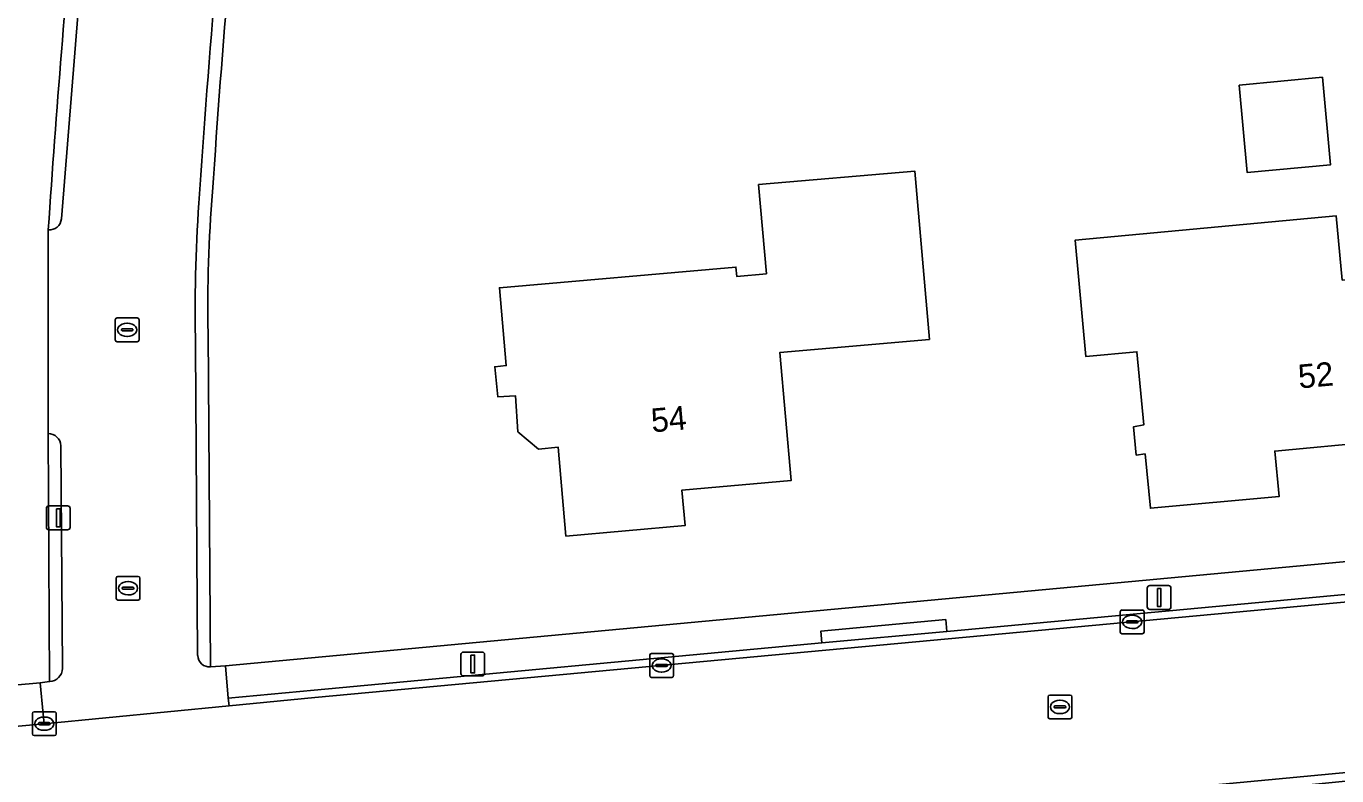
# Model space of a CAD drawing. Extents: x 162156 to 163172, y 378995 to 380779.
# Drawn here: x 162325.6 to 162380.6, y 380632.2 to 380663.7 of the extents above; entities that cross this region are included whole.
import ezdxf

# ---------------------------------------------------------------- set-up
doc = ezdxf.new("R2010")
doc.units = 0
for name, color, linetype in [('IMGEO_Erf', 7, 'Continuous'), ('IMGEO_Kolk', 7, 'Continuous'), ('IMGEO_Lichtmast', 7, 'Continuous'), ('IMGEO_Pand', 7, 'Continuous'), ('IMGEO_Pand_nummerreeks', 7, 'Continuous'), ('IMGEO_Rijbaan_lokaal_gesloten', 7, 'Continuous'), ('IMGEO_Rijbaan_lokaal_open', 7, 'Continuous'), ('IMGEO_Rioolput', 7, 'Continuous'), ('IMGEO_Voetpad_open', 7, 'Continuous')]:
    doc.layers.add(name, color=color, linetype=linetype)

msp = doc.modelspace()

# ---------------------------------------------------------------- linework, layer by layer
at = {"layer": 'IMGEO_Erf'}
for points in [[(162376.484, 380661.264), (162379.983, 380661.591), (162380.326, 380657.914), (162376.827, 380657.587)], [(162363.48, 380650.578), (162357.203, 380650.031), (162357.671, 380644.651), (162353.088, 380644.251), (162353.218, 380642.756), (162348.214, 380642.32), (162347.889, 380646.056), (162347.058, 380645.965), (162346.202, 380646.698), (162346.103, 380648.206), (162345.363, 380648.161), (162345.227, 380649.428), (162345.712, 380649.479), (162345.426, 380652.752), (162355.358, 380653.617), (162355.391, 380653.228), (162356.636, 380653.336), (162356.309, 380657.081), (162362.864, 380657.652)], [(162388.495, 380653.791), (162388.751, 380651.01), (162389.209, 380646.031), (162382.252, 380645.37), (162382.145, 380646.271), (162377.984, 380645.891), (162378.165, 380643.978), (162372.76, 380643.485), (162372.536, 380645.772), (162372.166, 380645.718), (162372.052, 380646.911), (162372.486, 380646.993), (162372.198, 380650.062), (162370.052, 380649.857), (162369.599, 380654.743), (162380.566, 380655.767), (162380.818, 380653.074)]]:
    msp.add_lwpolyline(points, close=True, dxfattribs=at)
for points in [[(162313.193, 380634.993), (162326.139, 380636.156), (162326.53, 380636.206), (162326.471, 380646.623), (162326.48, 380655.187)], [(162333.191, 380650.844), (162333.284, 380636.819), (162333.922, 380636.869), (162421.612, 380645.024), (162422.469, 380645.107), (162421.979, 380654.811)]]:
    msp.add_lwpolyline(points, dxfattribs=at)
for centre, radius, start, end in [((162806.048, 380625.746), 473.688, 174.0115, 176.24301), ((162859.206, 380619.711), 533.906, 174.58014, 176.19009), ((162390.909, 380652), 57.729, 175.24639, 181.14729)]:
    msp.add_arc(centre, radius, start, end, dxfattribs=at)
at = {"layer": 'IMGEO_Kolk'}
for p, q in [((162329.29, 380650.556), (162329.29, 380651.408)), ((162329.365, 380651.482), (162330.217, 380651.482)), ((162330.291, 380651.408), (162330.291, 380650.556)), ((162329.549, 380650.976), (162329.549, 380650.988)), ((162329.987, 380650.939), (162329.589, 380650.939)), ((162329.592, 380651.025), (162329.99, 380651.025)), ((162329.778, 380651.262), (162329.803, 380651.262)), ((162330.033, 380650.988), (162330.033, 380650.976)), ((162330.217, 380650.482), (162329.365, 380650.482)), ((162329.801, 380650.702), (162329.776, 380650.702)), ((162329.327, 380639.699), (162329.327, 380640.551)), ((162329.402, 380640.625), (162330.254, 380640.625)), ((162329.815, 380640.405), (162329.84, 380640.405)), ((162330.328, 380640.551), (162330.328, 380639.699)), ((162329.586, 380640.119), (162329.586, 380640.131)), ((162330.024, 380640.082), (162329.626, 380640.082)), ((162329.629, 380640.168), (162330.027, 380640.168)), ((162329.838, 380639.845), (162329.813, 380639.845)), ((162330.07, 380640.131), (162330.07, 380640.119)), ((162330.254, 380639.625), (162329.402, 380639.625)), ((162371.493, 380638.285), (162371.493, 380639.137)), ((162371.568, 380639.211), (162372.42, 380639.211)), ((162371.752, 380638.705), (162371.752, 380638.717)), ((162371.795, 380638.754), (162372.193, 380638.754)), ((162371.981, 380638.991), (162372.006, 380638.991)), ((162372.236, 380638.717), (162372.236, 380638.705)), ((162372.494, 380639.137), (162372.494, 380638.285)), ((162372.42, 380638.211), (162371.568, 380638.211)), ((162372.19, 380638.668), (162371.792, 380638.668)), ((162372.004, 380638.431), (162371.979, 380638.431)), ((162351.736, 380636.456), (162351.736, 380637.308)), ((162351.811, 380637.382), (162352.663, 380637.382)), ((162352.224, 380637.162), (162352.249, 380637.162)), ((162352.737, 380637.308), (162352.737, 380636.456)), ((162351.995, 380636.876), (162351.995, 380636.888)), ((162352.433, 380636.839), (162352.035, 380636.839)), ((162352.038, 380636.925), (162352.436, 380636.925)), ((162352.247, 380636.602), (162352.222, 380636.602)), ((162352.479, 380636.888), (162352.479, 380636.876)), ((162352.663, 380636.382), (162351.811, 380636.382)), ((162325.81, 380634.01), (162325.81, 380634.862)), ((162325.885, 380634.936), (162326.737, 380634.936)), ((162326.811, 380634.862), (162326.811, 380634.01)), ((162326.069, 380634.43), (162326.069, 380634.442)), ((162326.507, 380634.393), (162326.109, 380634.393)), ((162326.112, 380634.479), (162326.51, 380634.479)), ((162326.298, 380634.716), (162326.323, 380634.716)), ((162326.553, 380634.442), (162326.553, 380634.43)), ((162326.737, 380633.936), (162325.885, 380633.936)), ((162326.321, 380634.156), (162326.296, 380634.156))]:
    msp.add_line(p, q, dxfattribs=at)
for points in [[(162329.29, 380650.556), (162329.29, 380651.408)], [(162329.365, 380651.482), (162330.217, 380651.482)], [(162330.291, 380651.408), (162330.291, 380650.556)], [(162330.217, 380650.482), (162329.365, 380650.482)], [(162329.327, 380639.699), (162329.327, 380640.551)], [(162329.402, 380640.625), (162330.254, 380640.625)], [(162330.328, 380640.551), (162330.328, 380639.699)], [(162330.254, 380639.625), (162329.402, 380639.625)], [(162371.493, 380638.285), (162371.493, 380639.137)], [(162371.568, 380639.211), (162372.42, 380639.211)], [(162372.494, 380639.137), (162372.494, 380638.285)], [(162372.42, 380638.211), (162371.568, 380638.211)], [(162351.736, 380636.456), (162351.736, 380637.308)], [(162351.811, 380637.382), (162352.663, 380637.382)], [(162352.737, 380637.308), (162352.737, 380636.456)], [(162352.663, 380636.382), (162351.811, 380636.382)], [(162325.81, 380634.01), (162325.81, 380634.862)], [(162325.885, 380634.936), (162326.737, 380634.936)], [(162326.811, 380634.862), (162326.811, 380634.01)], [(162326.737, 380633.936), (162325.885, 380633.936)]]:
    msp.add_lwpolyline(points, dxfattribs=at)
for centre, radius, start, end in [((162329.367, 380651.406), 0.0765, 91.552, 178.448), ((162329.367, 380651.406), 0.0765, 91.552, 178.448), ((162330.215, 380651.406), 0.0765, 1.552, 88.448), ((162330.215, 380651.406), 0.0765, 1.552, 88.448), ((162329.589, 380650.985), 0.0403, 85.8775, 175.7526), ((162329.586, 380650.975), 0.0366, 178.938, 274.7102), ((162329.99, 380650.982), 0.043, 264.8664, 352.4533), ((162329.994, 380650.987), 0.0386, 1.7309, 96.639), ((162329.367, 380650.558), 0.0765, 181.552, 268.448), ((162329.367, 380650.558), 0.0765, 181.552, 268.448), ((162330.215, 380650.558), 0.0765, 271.552, 358.448), ((162330.215, 380650.558), 0.0765, 271.552, 358.448), ((162329.404, 380640.549), 0.0765, 91.552, 178.448), ((162329.404, 380640.549), 0.0765, 91.552, 178.448), ((162330.252, 380640.549), 0.0765, 1.552, 88.448), ((162330.252, 380640.549), 0.0765, 1.552, 88.448), ((162329.626, 380640.128), 0.0403, 85.8775, 175.7526), ((162329.623, 380640.118), 0.0366, 178.938, 274.7102), ((162330.027, 380640.125), 0.043, 264.8664, 352.4533), ((162330.031, 380640.13), 0.0386, 1.7309, 96.639), ((162329.404, 380639.701), 0.0765, 181.552, 268.448), ((162329.404, 380639.701), 0.0765, 181.552, 268.448), ((162330.252, 380639.701), 0.0765, 271.552, 358.448), ((162330.252, 380639.701), 0.0765, 271.552, 358.448), ((162371.57, 380639.135), 0.0765, 91.552, 178.448), ((162371.57, 380639.135), 0.0765, 91.552, 178.448), ((162371.792, 380638.714), 0.0403, 85.8775, 175.7526), ((162372.197, 380638.716), 0.0386, 1.7309, 96.639), ((162372.418, 380639.135), 0.0765, 1.552, 88.448), ((162372.418, 380639.135), 0.0765, 1.552, 88.448), ((162371.57, 380638.287), 0.0765, 181.552, 268.448), ((162371.57, 380638.287), 0.0765, 181.552, 268.448), ((162371.789, 380638.704), 0.0366, 178.938, 274.7102), ((162372.193, 380638.711), 0.043, 264.8664, 352.4533), ((162372.418, 380638.287), 0.0765, 271.552, 358.448), ((162372.418, 380638.287), 0.0765, 271.552, 358.448), ((162351.813, 380637.306), 0.0765, 91.552, 178.448), ((162351.813, 380637.306), 0.0765, 91.552, 178.448), ((162352.661, 380637.306), 0.0765, 1.552, 88.448), ((162352.661, 380637.306), 0.0765, 1.552, 88.448), ((162352.035, 380636.885), 0.0403, 85.8775, 175.7526), ((162352.032, 380636.875), 0.0366, 178.938, 274.7102), ((162352.436, 380636.882), 0.043, 264.8664, 352.4533), ((162352.44, 380636.887), 0.0386, 1.7309, 96.639), ((162351.813, 380636.458), 0.0765, 181.552, 268.448), ((162351.813, 380636.458), 0.0765, 181.552, 268.448), ((162352.661, 380636.458), 0.0765, 271.552, 358.448), ((162352.661, 380636.458), 0.0765, 271.552, 358.448), ((162325.887, 380634.86), 0.0765, 91.552, 178.448), ((162325.887, 380634.86), 0.0765, 91.552, 178.448), ((162326.735, 380634.86), 0.0765, 1.552, 88.448), ((162326.735, 380634.86), 0.0765, 1.552, 88.448), ((162326.109, 380634.439), 0.0403, 85.8775, 175.7526), ((162326.106, 380634.429), 0.0366, 178.938, 274.7102), ((162326.51, 380634.436), 0.043, 264.8664, 352.4533), ((162326.514, 380634.441), 0.0386, 1.7309, 96.639), ((162325.887, 380634.012), 0.0765, 181.552, 268.448), ((162325.887, 380634.012), 0.0765, 181.552, 268.448), ((162326.735, 380634.012), 0.0765, 271.552, 358.448), ((162326.735, 380634.012), 0.0765, 271.552, 358.448)]:
    msp.add_arc(centre, radius, start, end, dxfattribs=at)
for centre, major_axis, ratio, start_param, end_param in [((162329.777, 380650.982), (-0.387, 0.002), 0.722429, 4.712389, 7.853982), ((162329.802, 380650.982), (-0.39, 0.002), 0.717154, 1.570796, 4.712389), ((162329.814, 380640.125), (-0.387, 0.002), 0.722429, 4.712389, 7.853982), ((162329.839, 380640.125), (-0.39, 0.002), 0.717154, 1.570796, 4.712389), ((162371.98, 380638.711), (-0.387, 0.002), 0.722429, 4.712389, 7.853982), ((162372.005, 380638.711), (-0.39, 0.002), 0.717154, 1.570796, 4.712389), ((162352.223, 380636.882), (-0.387, 0.002), 0.722429, 4.712389, 7.853982), ((162352.248, 380636.882), (-0.39, 0.002), 0.717154, 1.570796, 4.712389), ((162326.297, 380634.436), (-0.387, 0.002), 0.722429, 4.712389, 7.853982), ((162326.322, 380634.436), (-0.39, 0.002), 0.717154, 1.570796, 4.712389)]:
    msp.add_ellipse(centre, major_axis=major_axis, ratio=ratio, start_param=start_param, end_param=end_param, dxfattribs=at)
at = {"layer": 'IMGEO_Lichtmast'}
for p, q in [((162326.402, 380642.683), (162326.402, 380643.483)), ((162326.402, 380643.483), (162326.402, 380642.683)), ((162326.502, 380643.583), (162327.292, 380643.583)), ((162327.292, 380643.583), (162326.502, 380643.583)), ((162327.392, 380643.483), (162327.392, 380642.683)), ((162327.392, 380642.683), (162327.392, 380643.483)), ((162327.292, 380642.583), (162326.502, 380642.583)), ((162326.502, 380642.583), (162327.292, 380642.583)), ((162372.632, 380639.338), (162372.632, 380640.138)), ((162372.632, 380640.138), (162372.632, 380639.338)), ((162372.732, 380640.238), (162373.522, 380640.238)), ((162373.522, 380640.238), (162372.732, 380640.238)), ((162373.622, 380640.138), (162373.622, 380639.338)), ((162373.622, 380639.338), (162373.622, 380640.138)), ((162373.522, 380639.238), (162372.732, 380639.238)), ((162372.732, 380639.238), (162373.522, 380639.238)), ((162343.809, 380636.544), (162343.809, 380637.344)), ((162343.809, 380637.344), (162343.809, 380636.544)), ((162343.909, 380637.444), (162344.699, 380637.444)), ((162344.699, 380637.444), (162343.909, 380637.444)), ((162344.799, 380637.344), (162344.799, 380636.544)), ((162344.799, 380636.544), (162344.799, 380637.344)), ((162344.699, 380636.444), (162343.909, 380636.444)), ((162343.909, 380636.444), (162344.699, 380636.444))]:
    msp.add_line(p, q, dxfattribs=at)
for points in [[(162326.822, 380643.458), (162326.972, 380643.458), (162326.972, 380642.708), (162326.822, 380642.708), (162326.822, 380643.458)], [(162373.052, 380640.113), (162373.202, 380640.113), (162373.202, 380639.363), (162373.052, 380639.363), (162373.052, 380640.113)], [(162344.229, 380637.319), (162344.379, 380637.319), (162344.379, 380636.569), (162344.229, 380636.569), (162344.229, 380637.319)]]:
    msp.add_lwpolyline(points, dxfattribs=at)
for centre, start, end in [((162326.502, 380643.483), 90, 180), ((162326.502, 380643.483), 90, 180), ((162327.292, 380643.483), 0, 90), ((162327.292, 380643.483), 360, 90), ((162326.502, 380642.683), 180, 270), ((162326.502, 380642.683), 180, 270), ((162327.292, 380642.683), 270, 0), ((162327.292, 380642.683), 270, 0), ((162372.732, 380640.138), 90, 180), ((162372.732, 380640.138), 90, 180), ((162373.522, 380640.138), 0, 90), ((162373.522, 380640.138), 360, 90), ((162372.732, 380639.338), 180, 270), ((162372.732, 380639.338), 180, 270), ((162373.522, 380639.338), 270, 0), ((162373.522, 380639.338), 270, 0), ((162343.909, 380637.344), 90, 180), ((162343.909, 380637.344), 90, 180), ((162344.699, 380637.344), 0, 90), ((162344.699, 380637.344), 360, 90), ((162343.909, 380636.544), 180, 270), ((162343.909, 380636.544), 180, 270), ((162344.699, 380636.544), 270, 0), ((162344.699, 380636.544), 270, 0)]:
    msp.add_arc(centre, 0.1, start, end, dxfattribs=at)
at = {"layer": 'IMGEO_Pand'}
for points in [[(162376.484, 380661.264), (162376.827, 380657.587), (162380.326, 380657.914), (162379.983, 380661.591)], [(162348.214, 380642.32), (162353.218, 380642.756), (162353.088, 380644.251), (162357.671, 380644.651), (162357.203, 380650.031), (162363.48, 380650.578), (162362.864, 380657.652), (162356.309, 380657.081), (162356.636, 380653.336), (162355.391, 380653.228), (162355.358, 380653.617), (162345.426, 380652.752), (162345.712, 380649.479), (162345.227, 380649.428), (162345.363, 380648.161), (162346.103, 380648.206), (162346.202, 380646.698), (162347.058, 380645.965), (162347.889, 380646.056)], [(162388.751, 380651.01), (162388.495, 380653.791), (162380.818, 380653.074), (162380.566, 380655.767), (162369.599, 380654.743), (162370.052, 380649.857), (162372.198, 380650.062), (162372.486, 380646.993), (162372.052, 380646.911), (162372.166, 380645.718), (162372.536, 380645.772), (162372.76, 380643.485), (162378.165, 380643.978), (162377.984, 380645.891), (162382.145, 380646.271), (162382.252, 380645.37), (162389.209, 380646.031)]]:
    msp.add_lwpolyline(points, close=True, dxfattribs=at)
at = {"layer": 'IMGEO_Rijbaan_lokaal_gesloten'}
for points in [[(162462.779, 380646.893), (162434.772, 380644.509), (162430.746, 380644.14), (162421.757, 380643.305), (162411.727, 380642.392), (162337.675, 380635.531), (162334.069, 380635.183), (162326.307, 380634.434), (162316.483, 380633.533), (162312.194, 380633.191)], [(162308.18, 380625.53), (162364.95, 380630.872), (162415.859, 380635.682), (162437.427, 380637.652)]]:
    msp.add_lwpolyline(points, dxfattribs=at)
msp.add_lwpolyline([(162437.074, 380637.227), (162437.462, 380637.263), (162437.427, 380637.652), (162415.859, 380635.682), (162364.95, 380630.872), (162308.18, 380625.53), (162308.221, 380625.096), (162318.483, 380626.064), (162325.57, 380626.732), (162328.269, 380626.987), (162329.764, 380627.128), (162364.046, 380630.361), (162364.931, 380630.444), (162365.42, 380630.567), (162371.399, 380631.11), (162371.841, 380631.104), (162372.405, 380631.16), (162388.242, 380632.742), (162429.631, 380636.541), (162431.034, 380636.67)], close=True, dxfattribs=at)
at = {"layer": 'IMGEO_Rijbaan_lokaal_open'}
for points in [[(162328.159, 380669.604), (162327.03, 380655.644)], [(162326.48, 380655.187), (162326.471, 380646.623)], [(162332.751, 380637.296), (162332.659, 380650.286)], [(162327.007, 380646.112), (162327.074, 380636.761)], [(162326.53, 380636.206), (162326.139, 380636.156), (162326.268, 380634.832), (162326.307, 380634.434), (162334.069, 380635.183), (162334.038, 380635.502), (162333.922, 380636.869), (162333.284, 380636.819)]]:
    msp.add_lwpolyline(points, dxfattribs=at)
msp.add_lwpolyline([(162415.962, 380643.099), (162411.697, 380642.711), (162393.688, 380641.042), (162382.287, 380639.986), (162364.212, 380638.311), (162358.96, 380637.825), (162337.644, 380635.85), (162334.038, 380635.502), (162334.069, 380635.183), (162337.675, 380635.531), (162411.727, 380642.392), (162421.757, 380643.305), (162421.728, 380643.624), (162419.72, 380643.441)], close=True, dxfattribs=at)
for centre, radius, start, end in [((162880.043, 380619.242), 548.496, 174.14115, 176.12624), ((162403.824, 380651.624), 71.177, 176.23553, 181.07699), ((162326.534, 380655.681), 0.497, 263.7704, 355.6766), ((162326.474, 380646.09), 0.533, 2.3672, 90.3684), ((162333.25, 380637.317), 0.499, 182.4332, 273.9139), ((162326.508, 380636.771), 0.566, 272.2057, 358.9412)]:
    msp.add_arc(centre, radius, start, end, dxfattribs=at)
at = {"layer": 'IMGEO_Rioolput'}
for p, q in [((162368.462, 380634.713), (162368.462, 380635.565)), ((162368.537, 380635.639), (162369.389, 380635.639)), ((162368.95, 380635.419), (162368.975, 380635.419)), ((162369.463, 380635.565), (162369.463, 380634.713)), ((162368.721, 380635.133), (162368.721, 380635.145)), ((162369.159, 380635.096), (162368.761, 380635.096)), ((162368.764, 380635.182), (162369.162, 380635.182)), ((162368.973, 380634.859), (162368.948, 380634.859)), ((162369.205, 380635.145), (162369.205, 380635.133)), ((162369.389, 380634.639), (162368.537, 380634.639))]:
    msp.add_line(p, q, dxfattribs=at)
for points in [[(162368.462, 380634.713), (162368.462, 380635.565)], [(162368.537, 380635.639), (162369.389, 380635.639)], [(162369.463, 380635.565), (162369.463, 380634.713)], [(162369.389, 380634.639), (162368.537, 380634.639)]]:
    msp.add_lwpolyline(points, dxfattribs=at)
for centre, radius, start, end in [((162368.539, 380635.563), 0.0765, 91.552, 178.448), ((162368.539, 380635.563), 0.0765, 91.552, 178.448), ((162369.387, 380635.563), 0.0765, 1.552, 88.448), ((162369.387, 380635.563), 0.0765, 1.552, 88.448), ((162368.761, 380635.142), 0.0403, 85.8775, 175.7526), ((162368.758, 380635.132), 0.0366, 178.938, 274.7102), ((162369.162, 380635.139), 0.043, 264.8664, 352.4533), ((162369.166, 380635.144), 0.0386, 1.7309, 96.639), ((162368.539, 380634.715), 0.0765, 181.552, 268.448), ((162368.539, 380634.715), 0.0765, 181.552, 268.448), ((162369.387, 380634.715), 0.0765, 271.552, 358.448), ((162369.387, 380634.715), 0.0765, 271.552, 358.448)]:
    msp.add_arc(centre, radius, start, end, dxfattribs=at)
for centre, major_axis, ratio, start_param, end_param in [((162368.949, 380635.139), (-0.387, 0.002), 0.722429, 4.712389, 7.853982), ((162368.974, 380635.139), (-0.39, 0.002), 0.717154, 1.570796, 4.712389)]:
    msp.add_ellipse(centre, major_axis=major_axis, ratio=ratio, start_param=start_param, end_param=end_param, dxfattribs=at)
at = {"layer": 'IMGEO_Voetpad_open'}
for points in [[(162327.03, 380655.644), (162328.159, 380669.604)], [(162333.284, 380636.819), (162333.191, 380650.844)], [(162332.659, 380650.286), (162332.751, 380637.296)], [(162326.471, 380646.623), (162326.53, 380636.206)], [(162327.074, 380636.761), (162327.007, 380646.112)], [(162312.194, 380633.191), (162316.483, 380633.533), (162326.307, 380634.434), (162326.268, 380634.832), (162326.139, 380636.156), (162313.193, 380634.993)]]:
    msp.add_lwpolyline(points, dxfattribs=at)
for points in [[(162415.962, 380643.099), (162415.917, 380643.6), (162419.674, 380643.945), (162419.72, 380643.441), (162421.728, 380643.624), (162421.612, 380645.024), (162333.922, 380636.869), (162334.038, 380635.502), (162337.644, 380635.85), (162358.96, 380637.825), (162358.914, 380638.322), (162364.166, 380638.808), (162364.212, 380638.311), (162382.287, 380639.986), (162382.241, 380640.483), (162393.642, 380641.539), (162393.688, 380641.042), (162411.697, 380642.711)], [(162358.96, 380637.825), (162364.212, 380638.311), (162364.166, 380638.808), (162358.914, 380638.322)]]:
    msp.add_lwpolyline(points, close=True, dxfattribs=at)
for centre, radius, start, end in [((162880.043, 380619.242), 548.496, 174.14115, 176.12624), ((162806.048, 380625.746), 473.688, 174.0115, 176.24301), ((162859.206, 380619.711), 533.906, 174.58014, 176.19009), ((162390.909, 380652), 57.729, 175.24639, 181.14729), ((162403.824, 380651.624), 71.177, 176.23553, 181.07699), ((162326.534, 380655.681), 0.497, 263.7704, 355.6766), ((162326.474, 380646.09), 0.533, 2.3672, 90.3684), ((162333.25, 380637.317), 0.499, 182.4332, 273.9139), ((162326.508, 380636.771), 0.566, 272.2057, 358.9412)]:
    msp.add_arc(centre, radius, start, end, dxfattribs=at)

# ---------------------------------------------------------------- texts
at = {"layer": 'IMGEO_Pand_nummerreeks'}
for s, rotation, p in [('52', 5.218, (162379.01, 380648.515)), ('54', 4.9881, (162351.835, 380646.672))]:
    msp.add_text(s, height=1, rotation=rotation, dxfattribs=at).set_placement(p)

doc.saveas('drawing.dxf')
